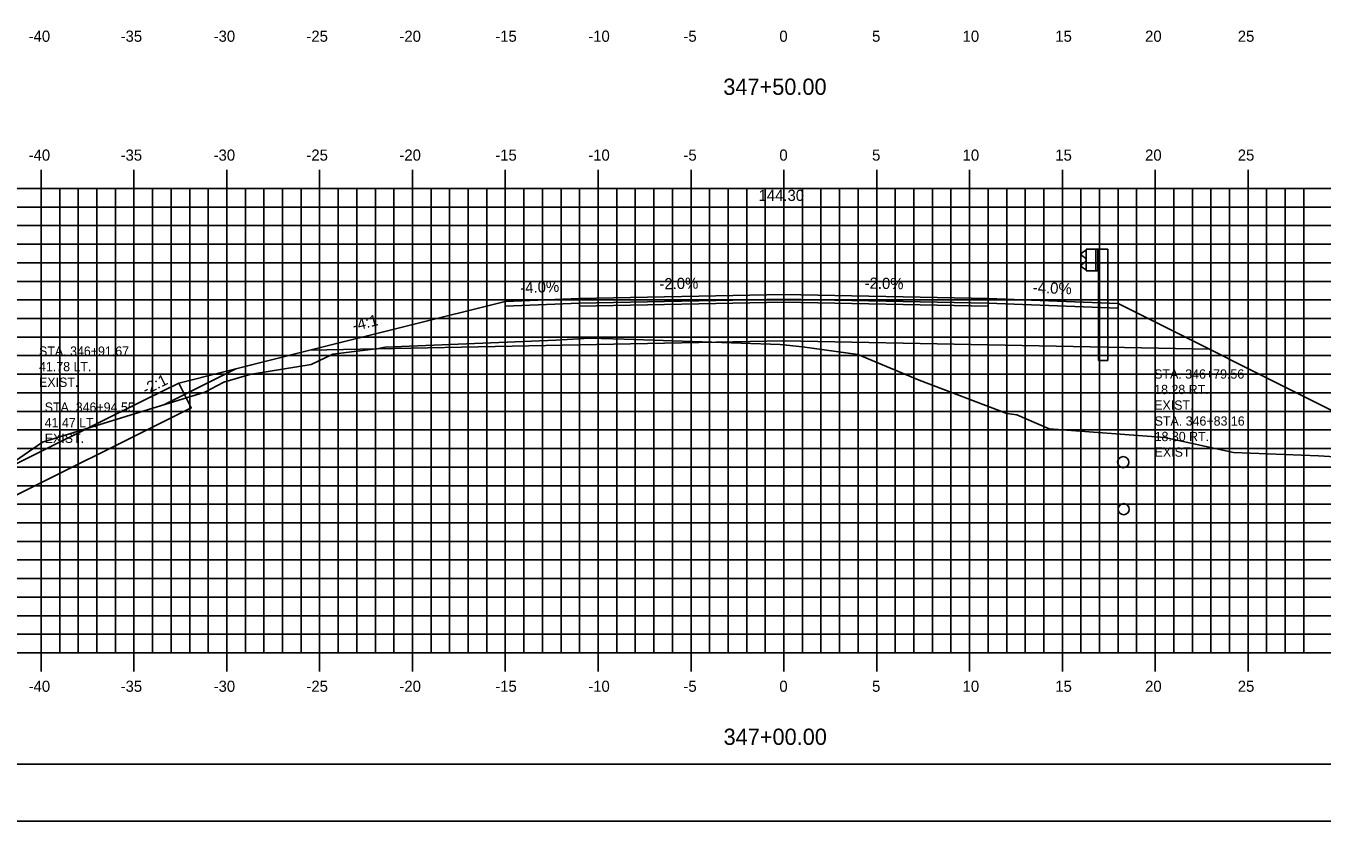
# Model space of a CAD drawing. Extents: x 1144085 to 1144255, y 608981 to 609091.
# Drawn here: x 1144127.5 to 1144197.3, y 608981.3 to 609024.1 of the extents above; entities that cross this region are included whole.
import ezdxf

# ---------------------------------------------------------------- set-up
doc = ezdxf.new("R2010")
doc.units = 0
for name, color, linetype in [('ANNOTATION', 7, 'Continuous'), ('BORDER', 7, 'Continuous'), ('D_Guardrail_Beam_Rt', 7, 'Continuous'), ('D_Guardrail_ConcBarrier', 7, 'Continuous'), ('D_Roadway_Centerline', 7, 'Continuous'), ('D_Roadway_Centerline_Text', 7, 'Continuous'), ('D_Roadway_Edge_Shoulder', 7, 'Continuous'), ('D_Roadway_Edge_TW', 7, 'Continuous'), ('D_Roadway_Pavement', 7, 'Continuous'), ('D_Roadway_SlopeLines', 7, 'Continuous'), ('D_Roadway_SubGrade', 7, 'Continuous'), ('D_Text_Monospaced', 7, 'Continuous'), ('H_V ANNOTATION', 7, 'Continuous'), ('MAJOR', 7, 'Continuous'), ('MINOR', 7, 'Continuous'), ('PATTERNING', 7, 'Continuous'), ('PLOT BOUNDARY', 7, 'Continuous'), ('S_Drainage_Invert', 7, 'Continuous'), ('S_Roadway_Centerline', 7, 'Continuous')]:
    doc.layers.add(name, color=color, linetype=linetype)

msp = doc.modelspace()

# ---------------------------------------------------------------- linework, layer by layer
msp.add_lwpolyline([(1144134.957, 609003.69), (1144138.826, 609005.625), (1144142.826, 609006.625), (1144153.348, 609009.255), (1144153.349, 609009.255), (1144157.349, 609009.415), (1144168.349, 609009.635), (1144179.349, 609009.415), (1144186.349, 609009.135), (1144191.266, 609006.677), (1144193.266, 609005.677), (1144203.692, 609000.464)])
at = {"layer": 'BORDER'}
msp.add_lwpolyline([(1144093.349, 608984.335), (1144253.349, 608984.335), (1144253.349, 609089.335), (1144093.349, 609089.335)], close=True, dxfattribs=at)
at = {"layer": 'D_Guardrail_Beam_Rt'}
for p, q in [((1144184.541, 609011.964), (1144184.397, 609011.864)), ((1144184.397, 609011.721), (1144184.593, 609011.585)), ((1144184.631, 609011.986), (1144184.557, 609011.971)), ((1144184.626, 609011.521), (1144184.626, 609011.45)), ((1144184.593, 609011.386), (1144184.397, 609011.25)), ((1144184.397, 609011.107), (1144184.541, 609011.007)), ((1144184.557, 609011), (1144184.631, 609010.986))]:
    msp.add_line(p, q, dxfattribs=at)
for centre, major_axis, start_param, end_param in [((1144184.448, 609011.793), (-0.0877, 0), 5.323254, 7.243116), ((1144184.565, 609011.93), (-0.0417, 0), 4.907132, 5.323254), ((1144184.547, 609011.521), (0.0789, 0), 0, 0.959931), ((1144184.547, 609011.45), (0.0789, 0), 5.323254, 6.283185), ((1144184.448, 609011.178), (-0.0877, 0), 5.323254, 7.243116), ((1144184.565, 609011.041), (-0.0417, 0), 0.959931, 1.376053)]:
    msp.add_ellipse(centre, major_axis=major_axis, ratio=0.995501, start_param=start_param, end_param=end_param, dxfattribs=at)
at = {"layer": 'D_Guardrail_ConcBarrier'}
for p, q in [((1144184.631, 609012.069), (1144185.318, 609012.069)), ((1144184.631, 609010.902), (1144184.631, 609012.069)), ((1144185.152, 609012.069), (1144185.152, 609010.902)), ((1144185.256, 609012.069), (1144185.256, 609010.902)), ((1144185.318, 609012.069), (1144185.789, 609012.069)), ((1144185.318, 609012.069), (1144185.318, 609010.902)), ((1144185.789, 609012.069), (1144185.789, 609006.069)), ((1144185.318, 609010.902), (1144184.631, 609010.902)), ((1144185.297, 609006.069), (1144185.297, 609010.902)), ((1144185.297, 609006.069), (1144185.789, 609006.069))]:
    msp.add_line(p, q, dxfattribs=at)
at = {"layer": 'D_Roadway_Edge_Shoulder'}
for points in [[(1144157.349, 609009.415), (1144153.349, 609009.255), (1144153.349, 609009.005), (1144157.349, 609009.165)], [(1144179.349, 609009.415), (1144186.349, 609009.135), (1144186.349, 609008.885), (1144179.349, 609009.165)]]:
    msp.add_lwpolyline(points, close=True, dxfattribs=at)
at = {"layer": 'D_Roadway_Edge_TW'}
msp.add_lwpolyline([(1144157.349, 609009.165), (1144157.349, 609009.415), (1144168.349, 609009.635), (1144179.349, 609009.415), (1144179.349, 609009.165), (1144168.349, 609009.385)], close=True, dxfattribs=at)
at = {"layer": 'D_Roadway_Pavement'}
msp.add_lwpolyline([(1144157.349, 609008.999), (1144157.349, 609009.165), (1144168.349, 609009.385), (1144179.349, 609009.165), (1144179.349, 609008.999), (1144168.349, 609009.219)], close=True, dxfattribs=at)
at = {"layer": 'D_Roadway_SlopeLines'}
for points in [[(1144142.826, 609006.625), (1144135.766, 609004.86)], [(1144191.266, 609006.677), (1144193.266, 609005.677)], [(1144193.266, 609005.677), (1144203.692, 609000.464)]]:
    msp.add_lwpolyline(points, dxfattribs=at)
at = {"layer": 'D_Roadway_SubGrade'}
for points in [[(1144157.349, 609008.999), (1144157.349, 609009.165), (1144153.349, 609009.005), (1144153.349, 609009.255), (1144153.348, 609009.255), (1144142.826, 609006.625), (1144157.349, 609006.915)], [(1144157.349, 609006.915), (1144157.349, 609008.999), (1144168.349, 609009.219), (1144179.349, 609008.999), (1144179.349, 609006.915), (1144168.349, 609007.135)], [(1144179.349, 609008.999), (1144179.349, 609009.165), (1144186.349, 609008.885), (1144186.349, 609009.135), (1144186.349, 609009.135), (1144191.266, 609006.677), (1144179.349, 609006.915)]]:
    msp.add_lwpolyline(points, close=True, dxfattribs=at)
at = {"layer": 'MAJOR'}
for p, q in [((1144128.349, 609016.337), (1144128.349, 609015.335)), ((1144133.349, 609016.337), (1144133.349, 609015.335)), ((1144138.349, 609016.337), (1144138.349, 609015.335)), ((1144143.349, 609016.337), (1144143.349, 609015.335)), ((1144148.349, 609016.337), (1144148.349, 609015.335)), ((1144153.349, 609016.337), (1144153.349, 609015.335)), ((1144158.349, 609016.337), (1144158.349, 609015.335)), ((1144163.349, 609016.337), (1144163.349, 609015.335)), ((1144168.349, 609016.337), (1144168.349, 609015.335)), ((1144173.349, 609016.337), (1144173.349, 609015.335)), ((1144178.349, 609016.337), (1144178.349, 609015.335)), ((1144183.349, 609016.337), (1144183.349, 609015.335)), ((1144188.349, 609016.337), (1144188.349, 609015.335)), ((1144193.349, 609016.337), (1144193.349, 609015.335)), ((1144098.349, 609015.335), (1144238.349, 609015.335)), ((1144098.349, 609015.335), (1144238.349, 609015.335)), ((1144128.349, 608990.335), (1144128.349, 609015.335)), ((1144133.349, 608990.335), (1144133.349, 609015.335)), ((1144138.349, 608990.335), (1144138.349, 609015.335)), ((1144143.349, 608990.335), (1144143.349, 609015.335)), ((1144148.349, 608990.335), (1144148.349, 609015.335)), ((1144153.349, 608990.335), (1144153.349, 609015.335)), ((1144158.349, 608990.335), (1144158.349, 609015.335)), ((1144163.349, 608990.335), (1144163.349, 609015.335)), ((1144168.349, 608990.335), (1144168.349, 609015.335)), ((1144173.349, 608990.335), (1144173.349, 609015.335)), ((1144178.349, 608990.335), (1144178.349, 609015.335)), ((1144183.349, 608990.335), (1144183.349, 609015.335)), ((1144188.349, 608990.335), (1144188.349, 609015.335)), ((1144193.349, 608990.335), (1144193.349, 609015.335)), ((1144098.349, 609010.335), (1144238.349, 609010.335)), ((1144098.349, 609005.335), (1144238.349, 609005.335)), ((1144098.349, 609000.335), (1144238.349, 609000.335)), ((1144098.349, 608995.335), (1144238.349, 608995.335)), ((1144098.349, 608990.335), (1144238.349, 608990.335)), ((1144098.349, 608990.335), (1144238.349, 608990.335)), ((1144128.349, 608989.333), (1144128.349, 608990.335)), ((1144133.349, 608989.333), (1144133.349, 608990.335)), ((1144138.349, 608989.333), (1144138.349, 608990.335)), ((1144143.349, 608989.333), (1144143.349, 608990.335)), ((1144148.349, 608989.333), (1144148.349, 608990.335)), ((1144153.349, 608989.333), (1144153.349, 608990.335)), ((1144158.349, 608989.333), (1144158.349, 608990.335)), ((1144163.349, 608989.333), (1144163.349, 608990.335)), ((1144168.349, 608989.333), (1144168.349, 608990.335)), ((1144173.349, 608989.333), (1144173.349, 608990.335)), ((1144178.349, 608989.333), (1144178.349, 608990.335)), ((1144183.349, 608989.333), (1144183.349, 608990.335)), ((1144188.349, 608989.333), (1144188.349, 608990.335)), ((1144193.349, 608989.333), (1144193.349, 608990.335))]:
    msp.add_line(p, q, dxfattribs=at)
at = {"layer": 'MINOR'}
for p, q in [((1144129.349, 608990.335), (1144129.349, 609015.335)), ((1144130.349, 608990.335), (1144130.349, 609015.335)), ((1144131.349, 608990.335), (1144131.349, 609015.335)), ((1144132.349, 608990.335), (1144132.349, 609015.335)), ((1144134.349, 608990.335), (1144134.349, 609015.335)), ((1144135.349, 608990.335), (1144135.349, 609015.335)), ((1144136.349, 608990.335), (1144136.349, 609015.335)), ((1144137.349, 608990.335), (1144137.349, 609015.335)), ((1144139.349, 608990.335), (1144139.349, 609015.335)), ((1144140.349, 608990.335), (1144140.349, 609015.335)), ((1144141.349, 608990.335), (1144141.349, 609015.335)), ((1144142.349, 608990.335), (1144142.349, 609015.335)), ((1144144.349, 608990.335), (1144144.349, 609015.335)), ((1144145.349, 608990.335), (1144145.349, 609015.335)), ((1144146.349, 608990.335), (1144146.349, 609015.335)), ((1144147.349, 608990.335), (1144147.349, 609015.335)), ((1144149.349, 608990.335), (1144149.349, 609015.335)), ((1144150.349, 608990.335), (1144150.349, 609015.335)), ((1144151.349, 608990.335), (1144151.349, 609015.335)), ((1144152.349, 608990.335), (1144152.349, 609015.335)), ((1144154.349, 608990.335), (1144154.349, 609015.335)), ((1144155.349, 608990.335), (1144155.349, 609015.335)), ((1144156.349, 608990.335), (1144156.349, 609015.335)), ((1144157.349, 608990.335), (1144157.349, 609015.335)), ((1144159.349, 608990.335), (1144159.349, 609015.335)), ((1144160.349, 608990.335), (1144160.349, 609015.335)), ((1144161.349, 608990.335), (1144161.349, 609015.335)), ((1144162.349, 608990.335), (1144162.349, 609015.335)), ((1144164.349, 608990.335), (1144164.349, 609015.335)), ((1144165.349, 608990.335), (1144165.349, 609015.335)), ((1144166.349, 608990.335), (1144166.349, 609015.335)), ((1144167.349, 608990.335), (1144167.349, 609015.335)), ((1144169.349, 608990.335), (1144169.349, 609015.335)), ((1144170.349, 608990.335), (1144170.349, 609015.335)), ((1144171.349, 608990.335), (1144171.349, 609015.335)), ((1144172.349, 608990.335), (1144172.349, 609015.335)), ((1144174.349, 608990.335), (1144174.349, 609015.335)), ((1144175.349, 608990.335), (1144175.349, 609015.335)), ((1144176.349, 608990.335), (1144176.349, 609015.335)), ((1144177.349, 608990.335), (1144177.349, 609015.335)), ((1144179.349, 608990.335), (1144179.349, 609015.335)), ((1144180.349, 608990.335), (1144180.349, 609015.335)), ((1144181.349, 608990.335), (1144181.349, 609015.335)), ((1144182.349, 608990.335), (1144182.349, 609015.335)), ((1144184.349, 608990.335), (1144184.349, 609015.335)), ((1144185.349, 608990.335), (1144185.349, 609015.335)), ((1144186.349, 608990.335), (1144186.349, 609015.335)), ((1144187.349, 608990.335), (1144187.349, 609015.335)), ((1144189.349, 608990.335), (1144189.349, 609015.335)), ((1144190.349, 608990.335), (1144190.349, 609015.335)), ((1144191.349, 608990.335), (1144191.349, 609015.335)), ((1144192.349, 608990.335), (1144192.349, 609015.335)), ((1144194.349, 608990.335), (1144194.349, 609015.335)), ((1144195.349, 608990.335), (1144195.349, 609015.335)), ((1144196.349, 608990.335), (1144196.349, 609015.335)), ((1144098.349, 609014.335), (1144238.349, 609014.335)), ((1144098.349, 609013.335), (1144238.349, 609013.335)), ((1144098.349, 609012.335), (1144238.349, 609012.335)), ((1144098.349, 609011.335), (1144238.349, 609011.335)), ((1144098.349, 609009.335), (1144238.349, 609009.335)), ((1144098.349, 609008.335), (1144238.349, 609008.335)), ((1144098.349, 609007.335), (1144238.349, 609007.335)), ((1144098.349, 609006.335), (1144238.349, 609006.335)), ((1144098.349, 609004.335), (1144238.349, 609004.335)), ((1144098.349, 609003.335), (1144238.349, 609003.335)), ((1144098.349, 609002.335), (1144238.349, 609002.335)), ((1144098.349, 609001.335), (1144238.349, 609001.335)), ((1144098.349, 608999.335), (1144238.349, 608999.335)), ((1144098.349, 608998.335), (1144238.349, 608998.335)), ((1144098.349, 608997.335), (1144238.349, 608997.335)), ((1144098.349, 608996.335), (1144238.349, 608996.335)), ((1144098.349, 608994.335), (1144238.349, 608994.335)), ((1144098.349, 608993.335), (1144238.349, 608993.335)), ((1144098.349, 608992.335), (1144238.349, 608992.335)), ((1144098.349, 608991.335), (1144238.349, 608991.335))]:
    msp.add_line(p, q, dxfattribs=at)
at = {"layer": 'PATTERNING'}
msp.add_lwpolyline([(1144125.491, 608999.771), (1144133.976, 609003.969), (1144135.766, 609004.86), (1144136.435, 609003.517), (1144125.475, 608998.062), (1144125.491, 608999.171)], close=True, dxfattribs=at)
at = {"layer": 'PLOT BOUNDARY'}
msp.add_lwpolyline([(1144085.256, 608981.276), (1144255.256, 608981.276), (1144255.256, 609091.276), (1144085.256, 609091.276)], close=True, dxfattribs=at)
at = {"layer": 'S_Drainage_Invert'}
for centre in [(1144186.626, 609000.6), (1144186.651, 608998.069)]:
    msp.add_circle(centre, 0.3, dxfattribs=at)
at = {"layer": 'S_Roadway_Centerline'}
msp.add_lwpolyline([(1144126.684, 609000.467), (1144128.429, 609001.677), (1144137.162, 609004.37), (1144138.187, 609004.913), (1144139.586, 609005.314), (1144139.804, 609005.365), (1144142.891, 609005.862), (1144144.061, 609006.414), (1144146.521, 609006.718), (1144146.884, 609006.785), (1144156.07, 609007.174), (1144157.898, 609007.271), (1144159.745, 609007.217), (1144168.152, 609006.944), (1144169.357, 609006.804), (1144172.328, 609006.403), (1144175.635, 609005.008), (1144180.36, 609003.224), (1144180.891, 609003.149), (1144182.638, 609002.401), (1144188.874, 609001.925), (1144192.559, 609001.123), (1144197.135, 609000.938), (1144200.427, 609000.749)], dxfattribs=at)

# ---------------------------------------------------------------- texts
at = {"layer": 'ANNOTATION'}
for s, rotation, p in [('-4.0%', 2.29061, (1144154.165, 609009.689)), ('-2.0%', 1.14576, (1144161.652, 609009.902)), ('-2.0%', 358.85424, (1144172.692, 609009.949)), ('-4.0%', 357.70939, (1144181.745, 609009.72)), ('-4:1', 14.03624, (1144145.199, 609007.649)), ('-2:1', 26.56505, (1144133.986, 609004.21))]:
    msp.add_text(s, height=0.6, rotation=rotation, dxfattribs=at).set_placement(p)
at = {"layer": 'D_Roadway_Centerline'}
for s, p in [('C', (1144168.344, 609009.635)), ('L', (1144168.349, 609009.628))]:
    msp.add_text(s, height=0.0146, dxfattribs=at).set_placement(p)
at = {"layer": 'D_Roadway_Centerline_Text'}
msp.add_text('144.30', height=0.6, dxfattribs=at).set_placement((1144166.985, 609014.667))
at = {"layer": 'D_Text_Monospaced'}
for s, height, p in [('STA. 346+91.67', 0.49998, (1144128.235, 609006.329)), ('41.78 LT.', 0.5, (1144128.235, 609005.495)), ('EXIST. ', 0.5, (1144128.235, 609004.655)), ('STA. 346+79.56', 0.49998, (1144188.293, 609005.098)), ('18.28 RT.', 0.5, (1144188.293, 609004.264)), ('STA. 346+94.55', 0.49998, (1144128.541, 609003.313)), ('EXIST. ', 0.5, (1144188.293, 609003.424)), ('STA. 346+83.16', 0.49998, (1144188.317, 609002.567)), ('41.47 LT.', 0.5, (1144128.541, 609002.479)), ('EXIST. ', 0.5, (1144128.541, 609001.639)), ('18.30 RT.', 0.5, (1144188.317, 609001.733)), ('EXIST. ', 0.5, (1144188.317, 609000.893))]:
    msp.add_text(s, height=height, dxfattribs=at).set_placement(p)
at = {"layer": 'H_V ANNOTATION'}
for s, height, p in [('-40', 0.6, (1144127.675, 609023.235)), ('-35', 0.6, (1144132.629, 609023.235)), ('-30', 0.6, (1144137.637, 609023.235)), ('-25', 0.6, (1144142.635, 609023.235)), ('-20', 0.6, (1144147.643, 609023.235)), ('-15', 0.6, (1144152.806, 609023.235)), ('-10', 0.6, (1144157.814, 609023.235)), ('-5', 0.6, (1144162.94, 609023.235)), ('0', 0.6, (1144168.108, 609023.235)), ('5', 0.6, (1144173.1, 609023.235)), ('10', 0.6, (1144177.975, 609023.235)), ('15', 0.6, (1144182.967, 609023.235)), ('20', 0.6, (1144187.803, 609023.235)), ('25', 0.6, (1144192.795, 609023.235)), ('347+50.00', 0.875, (1144165.087, 609020.378)), ('-40', 0.6, (1144127.675, 609016.835)), ('-35', 0.6, (1144132.629, 609016.835)), ('-30', 0.6, (1144137.637, 609016.835)), ('-25', 0.6, (1144142.635, 609016.835)), ('-20', 0.6, (1144147.643, 609016.835)), ('-15', 0.6, (1144152.806, 609016.835)), ('-10', 0.6, (1144157.814, 609016.835)), ('-5', 0.6, (1144162.94, 609016.835)), ('0', 0.6, (1144168.108, 609016.835)), ('5', 0.6, (1144173.1, 609016.835)), ('10', 0.6, (1144177.975, 609016.835)), ('15', 0.6, (1144182.967, 609016.835)), ('20', 0.6, (1144187.803, 609016.835)), ('25', 0.6, (1144192.795, 609016.835)), ('-40', 0.6, (1144127.675, 608988.235)), ('-35', 0.6, (1144132.629, 608988.235)), ('-30', 0.6, (1144137.637, 608988.235)), ('-25', 0.6, (1144142.635, 608988.235)), ('-20', 0.6, (1144147.643, 608988.235)), ('-15', 0.6, (1144152.806, 608988.235)), ('-10', 0.6, (1144157.814, 608988.235)), ('-5', 0.6, (1144162.94, 608988.235)), ('0', 0.6, (1144168.108, 608988.235)), ('5', 0.6, (1144173.1, 608988.235)), ('10', 0.6, (1144177.975, 608988.235)), ('15', 0.6, (1144182.967, 608988.235)), ('20', 0.6, (1144187.803, 608988.235)), ('25', 0.6, (1144192.795, 608988.235)), ('347+00.00', 0.875, (1144165.103, 608985.378))]:
    msp.add_text(s, height=height, dxfattribs=at).set_placement(p)
at = {"layer": 'S_Roadway_Centerline'}
for s, p in [('L', (1144157.889, 609007.264)), ('C', (1144157.893, 609007.271))]:
    msp.add_text(s, height=0.0146, dxfattribs=at).set_placement(p)

doc.saveas('drawing.dxf')
